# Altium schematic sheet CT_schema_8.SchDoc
size 277 x 170 mm
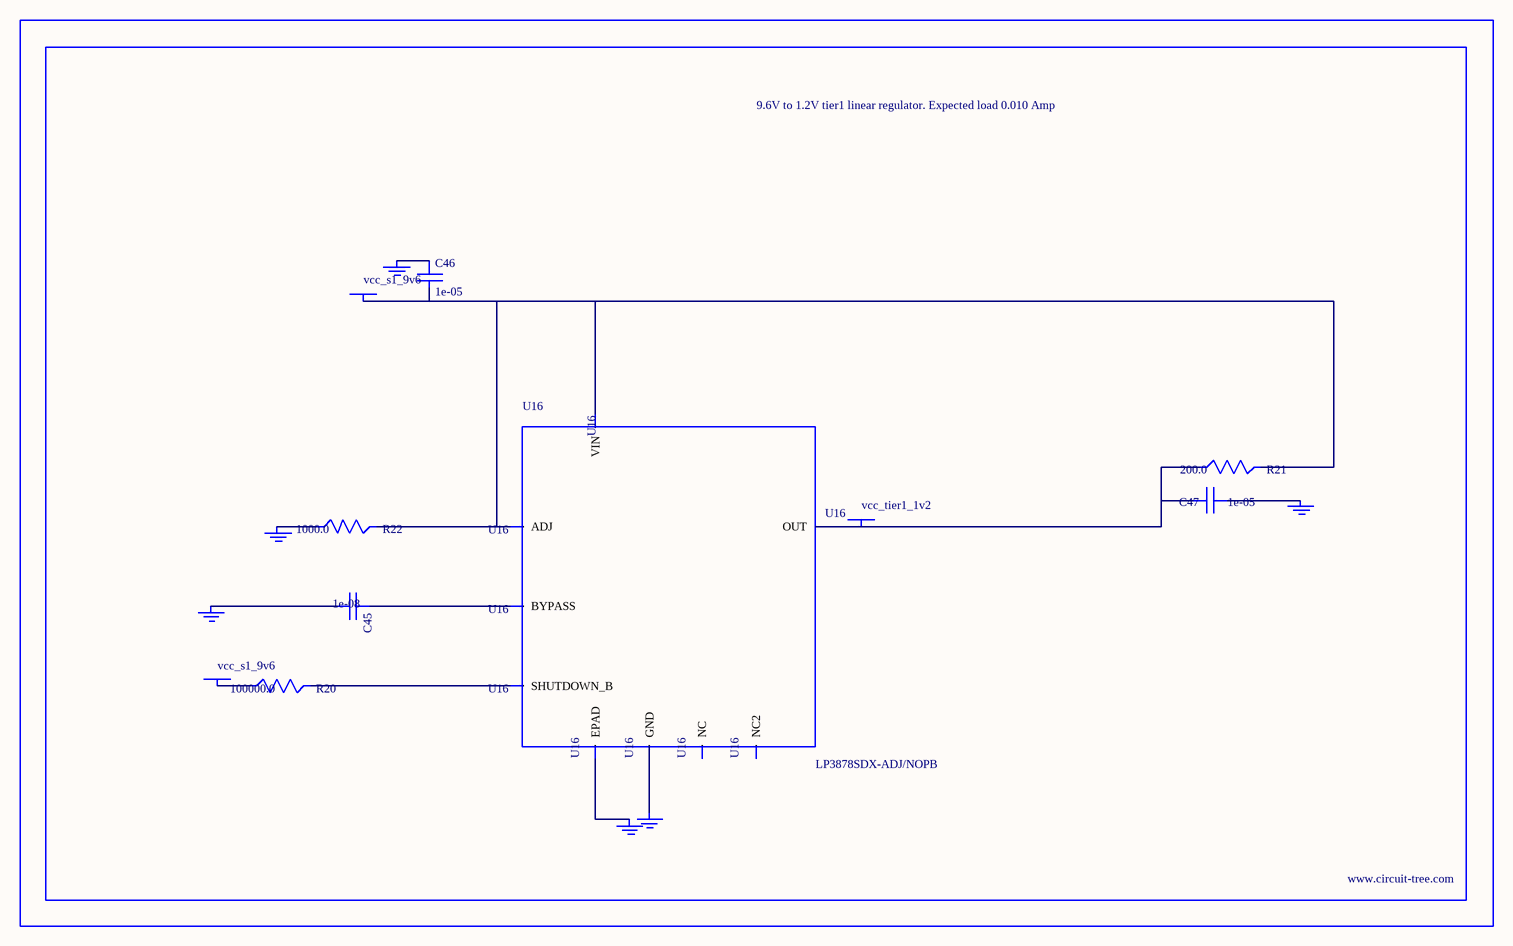
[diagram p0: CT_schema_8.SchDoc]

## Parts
BORDER7  (no value)
C45  1e-08  [C0402]
C46  1e-05  [C1206]
C47  1e-05  [C0805]
GND_INSTANCE_7_0  (no value)
GND_INSTANCE_7_1  (no value)
GND_INSTANCE_7_2  (no value)
GND_INSTANCE_7_3  (no value)
GND_INSTANCE_7_4  (no value)
GND_INSTANCE_7_5  (no value)
POWER_INSTANCE_7_0  vcc_s1_9v6
POWER_INSTANCE_7_1  vcc_s1_9v6
POWER_INSTANCE_7_2  vcc_tier1_1v2
R20  100000.0  [R0603]
R21  200.0  [R0603]
R22  1000.0  [R0603]
U16  LP3878SDX-ADJ/NOPB  [WSON-8]

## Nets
NetC45_1: C45.1 U16.1(BYPASS)
NetC45_2: C45.2 GND_INSTANCE_7_0.0(GND)
NetC46_1: C46.1 GND_INSTANCE_7_1.0(GND)
NetC46_2: C46.2 POWER_INSTANCE_7_0.0(PWR) R21.2 R22.2 U16.4(VIN) U16.6(ADJ)
NetC47_1: C47.1 GND_INSTANCE_7_2.0(GND)
NetC47_2: C47.2 POWER_INSTANCE_7_2.0(PWR) R21.1 U16.5(OUT)
NetGND_INSTANCE_7_3_0: GND_INSTANCE_7_3.0(GND) R22.1
NetGND_INSTANCE_7_4_0: GND_INSTANCE_7_4.0(GND) U16.PAD(EPAD)
NetGND_INSTANCE_7_5_0: GND_INSTANCE_7_5.0(GND) U16.3(GND)
NetPOWER_INSTANCE_7_1_0: POWER_INSTANCE_7_1.0(PWR) R20.1
NetR20_2: R20.2 U16.8(SHUTDOWN_B)

Not connected (* = marked no-connect by the designer): U16 2(NC) 7(NC2)

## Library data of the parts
BORDER7 = BORDER_PAGE7
C45 = C0402C103K3RAC
C46 = C1206C106K3RACTU
C47 = GRM219R60J106ME19D
GND_INSTANCE_7_0-GND_INSTANCE_7_5 = GND
POWER_INSTANCE_7_0-POWER_INSTANCE_7_2 = PWR
R20 = RC0603JR-07100KL
R21 = RC0603JR-07200RL
R22 = RC0603JR-071KL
